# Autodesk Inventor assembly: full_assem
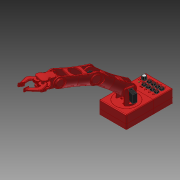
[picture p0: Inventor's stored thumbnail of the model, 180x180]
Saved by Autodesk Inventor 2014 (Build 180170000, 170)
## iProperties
Created: 2014-04
Part Number: full_assem
Document SubType Name: Assembly
Designer: t_emanb
Author: t_emanb
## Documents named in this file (7)
- C:\Users\t_emanb\Documents\3D printed arm\4th version\full_assem.iam
- C:\Users\t_emanb\Documents\3D printed arm\4th version\base_assem.iam
- C:\Users\t_emanb\Documents\3D printed arm\stock parts\servo_assem.iam
- C:\Users\t_emanb\Documents\3D printed arm\4th version\lower_assem.iam
- C:\Users\t_emanb\Documents\3D printed arm\4th version\mid_assem.iam
- C:\Users\t_emanb\Documents\3D printed arm\4th version\gripper_assem.iam
- C:\Users\t_emanb\Documents\3D printed arm\stock parts\rough_onoff.ipt
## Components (8 placed, 6 different names)
1. base_assem:1 [sub-assembly] — Mate:16, Mate:17, Mate:18, Mate:19, Mate:20, Mate:21, Mate:24, Mate:25, Flush:3
2. servo_assem:2 [sub-assembly] — Flush:1, Mate:7, Mate:8, Mate:16, Mate:17, Mate:18
3. servo_assem:3 [sub-assembly] — Mate:9, Mate:19, Mate:20, Mate:21
4. lower_assem:1 [sub-assembly] — Flush:1, Mate:7, Mate:8, Mate:9, Mate:10, Mate:11, Mate:12
5. mid_assem:1 [sub-assembly] — Mate:13, Mate:14, Mate:15, Flush:2, Mate:22, Mate:23
6. servo_assem:4 [sub-assembly] — Mate:10, Mate:11, Mate:12, Mate:13, Mate:14, Mate:15
7. gripper_assem:1 [sub-assembly] — Flush:2, Mate:22, Mate:23
8. rough_onoff:1 — Mate:24, Mate:25, Flush:3
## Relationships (22: Mate 19, Flush 3)
- Flush:1: servo_assem:2 ↔ lower_assem:1
- Mate:7: servo_assem:2 ↔ lower_assem:1
- Mate:8: servo_assem:2 ↔ lower_assem:1
- Mate:9: servo_assem:3 ↔ lower_assem:1
- Mate:10: lower_assem:1 ↔ servo_assem:4
- Mate:11: lower_assem:1 ↔ servo_assem:4
- Mate:12: lower_assem:1 ↔ servo_assem:4
- Mate:13: mid_assem:1 ↔ servo_assem:4
- Mate:14: mid_assem:1 ↔ servo_assem:4
- Mate:15: mid_assem:1 ↔ servo_assem:4
- Mate:16: base_assem:1 ↔ servo_assem:2
- Mate:17: base_assem:1 ↔ servo_assem:2
- Mate:18: base_assem:1 ↔ servo_assem:2
- Mate:19: base_assem:1 ↔ servo_assem:3
- Mate:20: base_assem:1 ↔ servo_assem:3
- Mate:21: base_assem:1 ↔ servo_assem:3
- Flush:2: mid_assem:1 ↔ gripper_assem:1
- Mate:22: mid_assem:1 ↔ gripper_assem:1
- Mate:23: mid_assem:1 ↔ gripper_assem:1
- Mate:24: base_assem:1 ↔ rough_onoff:1
- Mate:25: base_assem:1 ↔ rough_onoff:1
- Flush:3: base_assem:1 ↔ rough_onoff:1
